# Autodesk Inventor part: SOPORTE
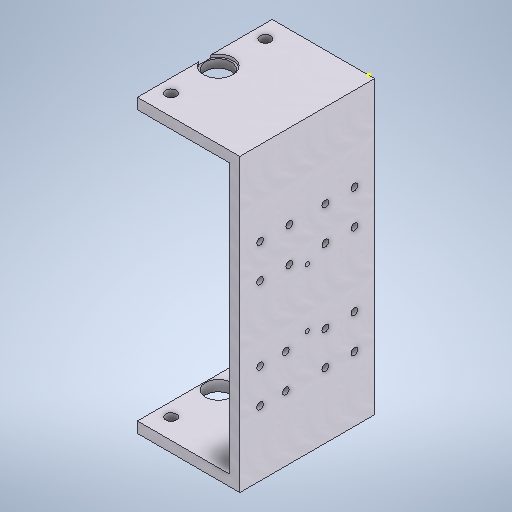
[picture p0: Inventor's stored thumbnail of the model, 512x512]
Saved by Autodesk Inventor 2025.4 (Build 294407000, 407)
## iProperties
Created: 2026-04
Part Number: SOPORTE
Material: Aluminum 6061, Welded
Document SubType Name: Modeling
Designer: PC
Density: 2.7 g/cm^3
Appearance: Weld - Aluminum
Author: PC
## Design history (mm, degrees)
sketch "Sketch1"
  geometry: L1 (4, -108)-(-4, -108); L2 (-4, -108)-(-4, 108); L3 (-4, 108)-(4, 108); L4 (4, 108)-(4, -108); L5 (4, -108)-(-4, 108); L6 (-4, -108)-(4, 108); L7 (4, 108)-(-72, 108); L8 (-72, 108)-(-72, 100); L9 (-72, 100)-(4, 100); L10 (4, 100)-(4, 108); L11 (4, -108)-(-72, -108); L12 (-72, -108)-(-72, -100); L13 (-72, -100)-(4, -100); L14 (4, -100)-(4, -108); 5 further points
  constraints: 28 end point, 6 parallel, 3 horizontal, 3 perpendicular, 2 midpoint, 1 point on line
  dimensions: "d0" = 8 distance of L2.end L3.end; "d1" = 216 distance of L1.end L2.end; "d2" = 76 distance of L9.end L8.end; "d3" = 8 distance of L8.end L7.end; "d4" = 8 distance of L11.end L12.end
extrude "Extrusion1" new body sketch "Sketch1" distance "d5" = 100; taper "d6" = 0 deg
sketch "Sketch2"
  geometry: L1 (0, 200)-(0, 0) reference; L2 (100, 200)-(100, 0) reference; L3 (15, 65.818)-(15, 40.218); L4 (15, 40.218)-(15, 53.018); L5 (15, 145.818)-(15, 120.218); L6 (15, 133.018)-(15, 53.018); L7 (85, 145.818)-(85, 120.502); C1 r 2.5 at (15, 145.818); C2 r 2.5 at (36.6, 145.818); C3 r 2.5 at (15, 120.218); C4 r 2.5 at (36.6, 120.502); C5 r 2.5 at (15, 65.818); C6 r 2.5 at (36.6, 65.818); C7 r 2.5 at (15, 40.218); C8 r 2.5 at (36.6, 40.502); C9 r 2.5 at (63.4, 145.818); C10 r 2.5 at (85, 145.818); C11 r 2.5 at (63.4, 120.218); C12 r 2.5 at (85, 120.502); C13 r 2.5 at (65.9, 65.818); C14 r 2.5 at (85, 65.818); C15 r 2.5 at (65.9, 40.218); C16 r 2.5 at (85, 40.218); 1 further point
  constraints: 16 centre point, 10 end point, 2 midpoint
  dimensions: "d7" = 5 diameter of C1; "d8" = 5 diameter of C2; "d9" = 5 diameter of C3; "d10" = 5 diameter of C4; "d11" = 21.6 distance of C2.centre L5.start; "d12" = 25.6 distance of L5.end L5.start; "d13" = 15 distance from line of L5.start L1; "d14" = 15 distance from line of L1 L5.end; "d15" = 21.6 horizontal distance of L5.end C4.centre; "d16" = 5 diameter of C5; "d17" = 5 diameter of C6; "d18" = 5 diameter of C7; "d19" = 5 diameter of C8; "d20" = 21.6 distance of C6.centre L3.start; "d21" = 25.6 distance of L3.end L3.start; "d22" = 21.6 horizontal distance of L3.end C8.centre; "d23" = 5 diameter of C9; "d24" = 5 diameter of C10; "d25" = 5 diameter of C11; "d26" = 5 diameter of C12; "d27" = 21.6 distance of L7.start C9.centre; "d28" = 25.6 distance of C11.centre C9.centre; "d29" = 21.6 horizontal distance of C11.centre L7.end; "d37" = 15 distance from line of L1 L3.start; "d38" = 15 distance from line of L2 L7.start; "d39" = 15 distance from line of L2 L7.end; "d42" = 15 distance from line of L1 L3.end; "d45" = 80 distance of L6.start L4.end
extrude "Extrusion2" cut sketch "Sketch2" extent not by distance; stored distance "d43" = 0; taper "d44" = 0 deg
sketch "Sketch3"
  geometry: L1 (0, 0)-(0, -100) reference; C1 r 11 at (10, -50); C2 r 9.5 at (10, -50); C3 r 4 at (10, -15); C4 r 4 at (10, -85); 4 further points
  constraints: 4 centre point, 1 coincident, 1 midpoint
  dimensions: "d47" = 22 diameter of C1; "d48" = 10 distance of point (0, -50) C1.centre; "d49" = 19 diameter of C2; "d54" = 8 diameter of C3; "d55" = 8 diameter of C4; "d56" = 35 distance of C1.centre C3.centre; "d57" = 35 distance of C4.centre C1.centre
extrude "Extrusion3" cut sketch "Sketch3" extent not by distance; stored distance "d50" = 0; taper "d51" = 0 deg
extrude "Extrusion4" cut sketch "Sketch3" distance "d52" = 2; taper "d53" = 0 deg
sketch "Sketch4"
  geometry: 1 further point
sketch "Sketch5"
  geometry: L1 (15, 120.218)-(15, 93.018); L2 (85, 120.502)-(15, 120.218); L3 (15, 93.018)-(50, 93.16); L4 (50, 93.16)-(49.933, 109.66); L5 (49.933, 109.66)-(40.244, 109.62); L6 (50, 93.16)-(50, 76.66); L7 (50, 76.66)-(38.59, 76.66); C1 r 2.5 at (15, 65.818) reference; C2 r 2.5 at (15, 120.218) reference; C3 r 2.5 at (85, 120.502) reference; C4 r 1.6 at (50, 70.881); C5 r 1.6 at (49.917, 113.73); 1 further point
  constraints: 14 end point, 3 perpendicular, 2 centre point, 2 vertical, 1 parallel
  dimensions: "d58" = 54.4 distance of C1.centre L1.start (derived); "d59" = 27.2 distance of L1.start L1.end; "d60" = 16.5 distance of L3.end L4.end; "d61" = 16.5 distance of L3.end L6.end; "d62" = 3.2 diameter of C4; "d63" = 3.2 diameter of C5; "d64" = 0 distance from line of C5.centre L4; "d65" = 0 distance from line of L6 C4.centre
extrude "Extrusion5" cut sketch "Sketch5" distance "d66" = 10; taper "d67" = 0 deg
body "Solid1"
